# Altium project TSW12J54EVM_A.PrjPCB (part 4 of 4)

## Sheet TSW12J54EVM_A_8_Hardware.SchDoc
size 431 x 279 mm; Date: Not shown in title block; ApprovedBy: Not shown in title block; CheckedBy: Not shown in title block; Author: Not shown in title block; CompanyName: Not shown in title block; Engineer: Not shown in title block; Organization: Not shown in title block; Address1: Not shown in title block; Address2: Not shown in title block; Address3: Not shown in title block; Address4: Not shown in title block; DocumentNumber: 8; Revision: Use project parameter SCH_Rev; SheetNumber: 8; SheetTotal: 8; PageSetup: Record=PageOptions¦CenterHorizontal=True¦CenterVertical=True¦PrintScale=1.00¦XCorrection=1.00¦YCorrection=1.00¦PrintKind=0¦BorderSize=5000000¦LeftOffset=0¦BottomOffset=0¦Orientation=2¦PaperLength=1000¦PaperWidth=1000¦Scale=100¦PaperSource=15¦PrintQuality=600¦MediaType=1¦DitherType=10¦PaperKind=Letter¦PrintScaleMode=1
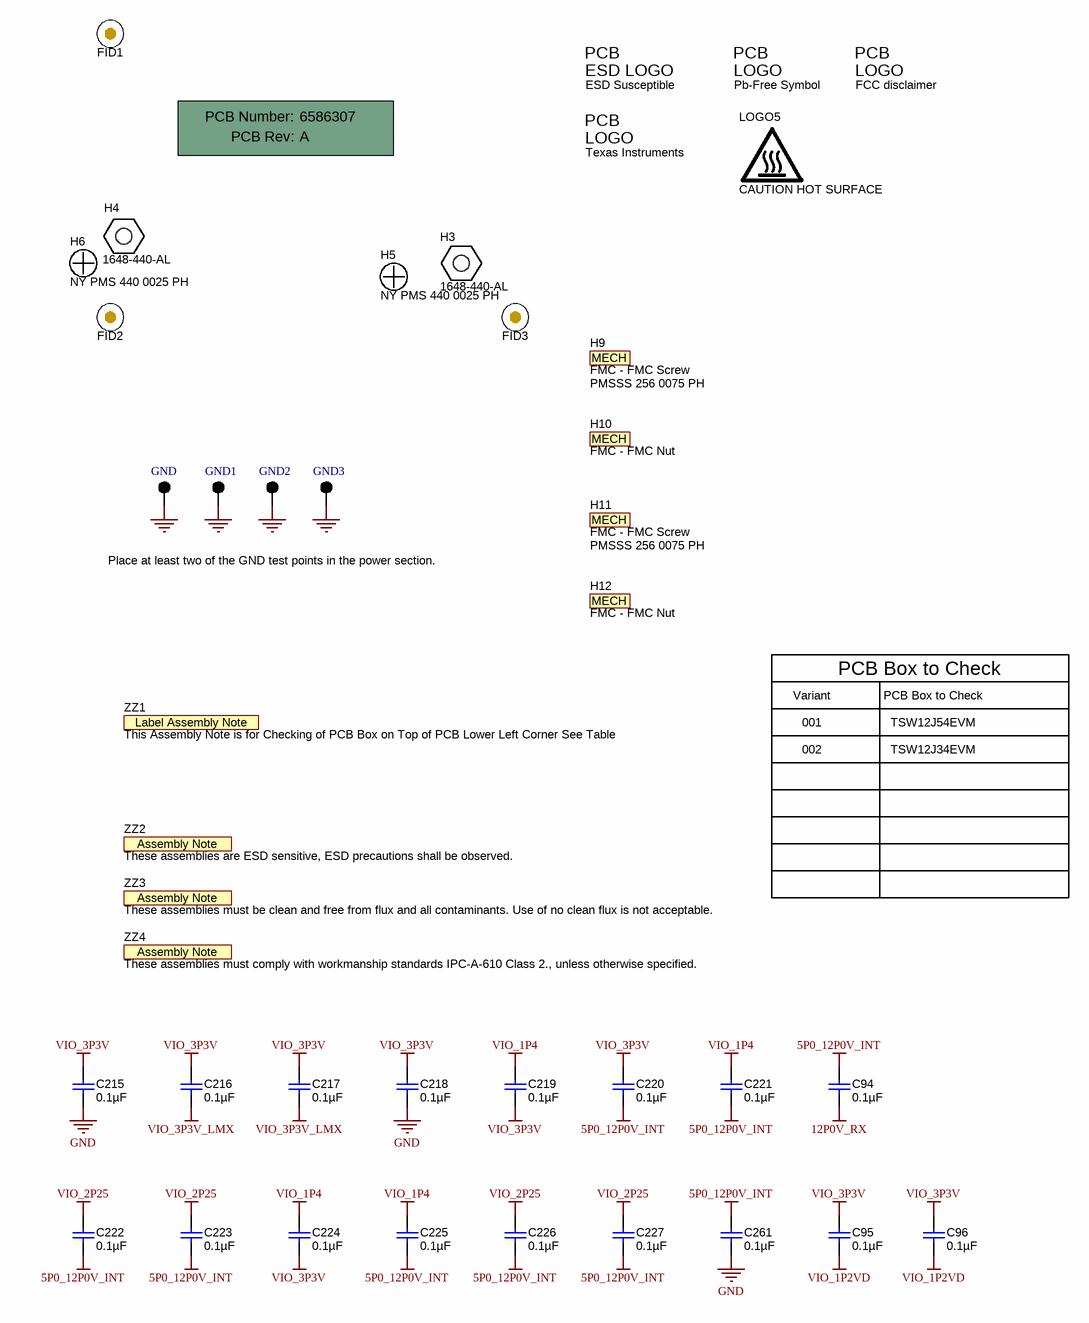
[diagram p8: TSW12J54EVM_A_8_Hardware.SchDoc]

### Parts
!PCB  Printed Circuit Board  (value not drawn)  (mechanical)
C94  ValueDisplayed: 0.1µF  [0402L]  (hidden comment: GRM155R71A104KA01D)
C95  ValueDisplayed: 0.1µF  [0402L]  (hidden comment: GRM155R71A104KA01D)
C96  ValueDisplayed: 0.1µF  [0402L]  (hidden comment: GRM155R71A104KA01D)
C215  ValueDisplayed: 0.1µF  [0402L]  (hidden comment: GRM155R71A104KA01D)
C216  ValueDisplayed: 0.1µF  [0402L]  (hidden comment: GRM155R71A104KA01D)
C217  ValueDisplayed: 0.1µF  [0402L]  (hidden comment: GRM155R71A104KA01D)
C218  ValueDisplayed: 0.1µF  [0402L]  (hidden comment: GRM155R71A104KA01D)
C219  ValueDisplayed: 0.1µF  [0402L]  (hidden comment: GRM155R71A104KA01D)
C220  ValueDisplayed: 0.1µF  [0402L]  (hidden comment: GRM155R71A104KA01D)
C221  ValueDisplayed: 0.1µF  [0402L]  (hidden comment: GRM155R71A104KA01D)
C222  ValueDisplayed: 0.1µF  [0402L]  (hidden comment: GRM155R71A104KA01D)
C223  ValueDisplayed: 0.1µF  [0402L]  (hidden comment: GRM155R71A104KA01D)
C224  ValueDisplayed: 0.1µF  [0402L]  (hidden comment: GRM155R71A104KA01D)
C225  ValueDisplayed: 0.1µF  [0402L]  (hidden comment: GRM155R71A104KA01D)
C226  ValueDisplayed: 0.1µF  [0402L]  (hidden comment: GRM155R71A104KA01D)
C227  ValueDisplayed: 0.1µF  [0402L]  (hidden comment: GRM155R71A104KA01D)
C261  ValueDisplayed: 0.1µF  [0402L]  (hidden comment: GRM155R71A104KA01D)
FID1  Fiducial  [Fiducial10-30]  (value not drawn)
FID2  Fiducial  [Fiducial10-30]  (value not drawn)
FID3  Fiducial  [Fiducial10-30]  (value not drawn)
GND  5011  [Keystone5011]  (value not drawn)
GND1  5011  [Keystone5011]  (value not drawn)
GND2  5011  [Keystone5011]  (value not drawn)
GND3  5011  [Keystone5011]  (value not drawn)
H3  1648-440-AL  [Keystone_1902C]
H4  1648-440-AL  [Keystone_1902C]
H5  NY PMS 440 0025 PH  [NY PMS 440 0025 PH]
H6  NY PMS 440 0025 PH  [NY PMS 440 0025 PH]
H9  FMC - FMC Screw  PartNumber: PMSSS 256 0075 PH  (mechanical)
H10  FMC - FMC Nut  (mechanical)
H11  FMC - FMC Screw  PartNumber: PMSSS 256 0075 PH  (mechanical)
H12  FMC - FMC Nut  (mechanical)
Logo1  ESD Susceptible  [ESD_Overlay_Small]  (no BOM)
Logo2  Texas Instruments  [TI_Symbol_Overlay_Small]  (no BOM)
Logo3  Pb-Free Symbol  [Pb-Free_Overlay_Small]  (no BOM)
Logo4  FCC disclaimer  [FCC_disclaimer]  (no BOM)
LOGO5  CAUTION HOT SURFACE  [IEC_HotSurface_Small]  (no BOM)
ZZ1  This Assembly Note is for Checking of PCB Box on Top of PCB Lower Left Corner See Table  [AssemblyNoteLabel]  (no BOM)
ZZ2  These assemblies are ESD sensitive, ESD precautions shall be observed.  [AssemblyNote]  (no BOM)
ZZ3  These assemblies must be clean and free from flux and all contaminants. Use of no clean flux is not acceptable.  [AssemblyNote]  (no BOM)
ZZ4  These assemblies must comply with workmanship standards IPC-A-610 Class 2., unless otherwise specified.  [AssemblyNote]  (no BOM)

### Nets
5P0_12P0V_INT: C94.1 C220.2 C221.2 C222.2 C223.2 C225.2 C226.2 C227.2 C261.1
12P0V_RX: C94.2
GND: C215.2 C218.2 C261.2 GND.1 GND1.1 GND2.1 GND3.1
VIO_1P2VD: C95.2 C96.2
VIO_1P4: C219.1 C221.1 C224.1 C225.1
VIO_2P25: C222.1 C223.1 C226.1 C227.1
VIO_3P3V: C95.1 C96.1 C215.1 C216.1 C217.1 C218.1 C219.2 C220.1 C224.2
VIO_3P3V_LMX: C216.2 C217.2

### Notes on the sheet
- Place at least two of the GND test points in the power section.
- Variant
- PCB Box to Check
- 001
- 002
- TSW12J54EVM
- TSW12J34EVM

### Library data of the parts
!PCB = PCB: Manufacturer: Any; PartNumber: 6586307; SymbolCreator: a0412235
C94-C96 C215-C227 C261 = GRM155R71A104KA01D: CAP, CERM, 0.1uF, 10V, +/-10%, X7R, 0402; Manufacturer: MuRata; Polarized: N; CompType: Capacitor; U/M: EA; Cap_F: 0.0000001; Tolerance_%: 10; TaMin_C: -55; TaMax_C: 125; Cap_Case: 0402
FID1-FID3 = Fiducial: Fiducial mark.  There is nothing to buy or mount.; SymbolCreator: codlsc
GND GND1-GND3 = 5011: Test Point, TH, Multipurpose, Black; Manufacturer: Keystone Electronics; CompType: Test Point Loop
H3 H4 = 1902C: Standoff, Round, 3/16"  x 1-3/16"L #4-40 Aluminum; Manufacturer: RAF; CompType: Hardware; U/M: EA
H5 H6 = NY PMS 440 0025 PH: Machine Screw, Round, #4-40 x 1/4, Nylon, Philips panhead; Manufacturer: B&F Fastener Supply; CompType: Hardware; SymbolCreator: codlsc; U/M: EA
H9 H11 = MechPart: MACHINE SCREW PAN PHILLIPS 2-56; Manufacturer: B&F Fastner Supply; SymbolCreator: codlsc; CompType: Mechanical; U/M: EA
H10 H12 = MechPart: HEX NUT 3/16" STN STEEL 2-56; Manufacturer: B & F Fastener Supply; PartNumber: HNSS256; SymbolCreator: codlsc; CompType: Mechanical; U/M: EA
Logo1 = ESD_Susceptible: ESD Susceptible Symbol; SymbolCreator: codlsc
Logo2 = TI_Logo: Texas Instrument Corporate Signature; SymbolCreator: codlsc
Logo3 = Pb-Free: SymbolCreator: a0412235
Logo4 = FCC_disclaimer: SymbolCreator: codlsc
LOGO5 = IEC_HotSurface: IEC 61010-1 Hot Surface Warning; SymbolCreator: a0412235
ZZ1 = AssemblyNoteLabel: SymbolCreator: a0412235
ZZ2-ZZ4 = AssemblyNote: SymbolCreator: codlsc

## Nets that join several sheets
5P0_12P0V_INT: TSW12J54EVM_A_5_Power (16 pins), TSW12J54EVM_A_8_Hardware (9 pins)
12P0V_RX: TSW12J54EVM_A_2_FMC (FMC_RX1.C35 FMC_RX1.C37), TSW12J54EVM_A_5_Power (EXT5V_FMC12V.3), TSW12J54EVM_A_8_Hardware (C94.2)
GND: TSW12J54EVM_A_1_ADC_IO (110 pins), TSW12J54EVM_A_2_FMC (164 pins), TSW12J54EVM_A_3_TRF3765 (64 pins), TSW12J54EVM_A_4_LMK04828 (33 pins), TSW12J54EVM_A_5_Power (80 pins), TSW12J54EVM_A_6_Power (20 pins), TSW12J54EVM_A_7_InterfaceControl (20 pins), TSW12J54EVM_A_8_Hardware (7 pins)
VIO_1P2VA: TSW12J54EVM_A_1_ADC_IO (18 pins), TSW12J54EVM_A_5_Power (C177.1 C188.1 L15.2)
VIO_1P2VD: TSW12J54EVM_A_1_ADC_IO (28 pins), TSW12J54EVM_A_5_Power (C189.1 C197.1 L16.2), TSW12J54EVM_A_8_Hardware (C95.2 C96.2)
VIO_1P4: TSW12J54EVM_A_5_Power (5 pins), TSW12J54EVM_A_8_Hardware (C219.1 C221.1 C224.1 C225.1)
VIO_1P9V: TSW12J54EVM_A_1_ADC_IO (20 pins), TSW12J54EVM_A_5_Power (6 pins), TSW12J54EVM_A_6_Power (R170.1 R173.1), TSW12J54EVM_A_7_InterfaceControl (C130.1 R123.2 U12.15)
VIO_2P25: TSW12J54EVM_A_5_Power (5 pins), TSW12J54EVM_A_8_Hardware (C222.1 C223.1 C226.1 C227.1)
VIO_3P3V: TSW12J54EVM_A_1_ADC_IO (15 pins), TSW12J54EVM_A_5_Power (C153.1 C163.1 L9.2), TSW12J54EVM_A_7_InterfaceControl (FTDI_3P3V.1 J3.2), TSW12J54EVM_A_8_Hardware (9 pins)
VIO_3P3V_LMK_CLK: TSW12J54EVM_A_4_LMK04828 (6 pins), TSW12J54EVM_A_5_Power (C116.1 C171.1 L13.2), TSW12J54EVM_A_7_InterfaceControl (R131.1)
VIO_3P3V_LMK_PLL: TSW12J54EVM_A_4_LMK04828 (16 pins), TSW12J54EVM_A_5_Power (C164.1 C165.1 L10.2)
VIO_3P3V_LMX: TSW12J54EVM_A_3_TRF3765 (19 pins), TSW12J54EVM_A_5_Power (C144.1 C152.1 L6.2), TSW12J54EVM_A_7_InterfaceControl (R130.1), TSW12J54EVM_A_8_Hardware (C216.2 C217.2)
VIO_3P75: TSW12J54EVM_A_1_ADC_IO (11 pins), TSW12J54EVM_A_6_Power (C280.1 C281.1 L43.2)
VIO_4P05V: TSW12J54EVM_A_5_Power (6 pins), TSW12J54EVM_A_6_Power (L35.1 L36.1)
VIO_-1P25: TSW12J54EVM_A_1_ADC_IO (10 pins), TSW12J54EVM_A_6_Power (C289.1 C290.1 L44.2)
ADC_OR_T0: TSW12J54EVM_A_1_ADC_IO (D2.2 OR.3 U2.25), TSW12J54EVM_A_2_FMC (FMC_RX1.G27)
ADC_OR_T1: TSW12J54EVM_A_1_ADC_IO (D4.2 OR.1 U2.26), TSW12J54EVM_A_2_FMC (FMC_RX1.D26)
D0_N: TSW12J54EVM_A_1_ADC_IO (C9.1), TSW12J54EVM_A_2_FMC (FMC_RX1.C6)
D0_P: TSW12J54EVM_A_1_ADC_IO (C7.1), TSW12J54EVM_A_2_FMC (FMC_RX1.C7)
D1_N: TSW12J54EVM_A_1_ADC_IO (C12.1), TSW12J54EVM_A_2_FMC (FMC_RX1.A2)
D1_P: TSW12J54EVM_A_1_ADC_IO (C10.1), TSW12J54EVM_A_2_FMC (FMC_RX1.A3)
D2_N: TSW12J54EVM_A_1_ADC_IO (C14.1), TSW12J54EVM_A_2_FMC (FMC_RX1.A6)
D2_P: TSW12J54EVM_A_1_ADC_IO (C13.1), TSW12J54EVM_A_2_FMC (FMC_RX1.A7)
D3_N: TSW12J54EVM_A_1_ADC_IO (C17.1), TSW12J54EVM_A_2_FMC (FMC_RX1.A10)
D3_P: TSW12J54EVM_A_1_ADC_IO (C15.1), TSW12J54EVM_A_2_FMC (FMC_RX1.A11)
D4_N: TSW12J54EVM_A_1_ADC_IO (C21.1), TSW12J54EVM_A_2_FMC (FMC_RX1.A14)
D4_P: TSW12J54EVM_A_1_ADC_IO (C20.1), TSW12J54EVM_A_2_FMC (FMC_RX1.A15)
D5_N: TSW12J54EVM_A_1_ADC_IO (C23.1), TSW12J54EVM_A_2_FMC (FMC_RX1.A18)
D5_P: TSW12J54EVM_A_1_ADC_IO (C22.1), TSW12J54EVM_A_2_FMC (FMC_RX1.A19)
D6_N: TSW12J54EVM_A_1_ADC_IO (C28.1), TSW12J54EVM_A_2_FMC (FMC_RX1.B16)
D6_P: TSW12J54EVM_A_1_ADC_IO (C26.1), TSW12J54EVM_A_2_FMC (FMC_RX1.B17)
D7_N: TSW12J54EVM_A_1_ADC_IO (C31.1), TSW12J54EVM_A_2_FMC (FMC_RX1.B12)
D7_P: TSW12J54EVM_A_1_ADC_IO (C29.1), TSW12J54EVM_A_2_FMC (FMC_RX1.B13)
DEV_CLK_N: TSW12J54EVM_A_1_ADC_IO (C263.2), TSW12J54EVM_A_4_LMK04828 (R160.2)
DEV_CLK_P: TSW12J54EVM_A_1_ADC_IO (C262.2), TSW12J54EVM_A_4_LMK04828 (R161.2)
DEVCLKARX_N: TSW12J54EVM_A_2_FMC (FMC_RX1.D5), TSW12J54EVM_A_4_LMK04828 (R60.2)
DEVCLKARX_P: TSW12J54EVM_A_2_FMC (FMC_RX1.D4), TSW12J54EVM_A_4_LMK04828 (R59.2)
DEVCLKBRX_N: TSW12J54EVM_A_2_FMC (FMC_RX1.G7), TSW12J54EVM_A_4_LMK04828 (R63.2)
DEVCLKBRX_P: TSW12J54EVM_A_2_FMC (FMC_RX1.G6), TSW12J54EVM_A_4_LMK04828 (R64.2)
FMC_DEVCLK_N: TSW12J54EVM_A_1_ADC_IO (C93.2), TSW12J54EVM_A_2_FMC (FMC_RX1.K29)
FMC_DEVCLK_P: TSW12J54EVM_A_1_ADC_IO (C92.2), TSW12J54EVM_A_2_FMC (FMC_RX1.K28)
FMC_SYSREF_N: TSW12J54EVM_A_1_ADC_IO (C91.2), TSW12J54EVM_A_2_FMC (FMC_RX1.K38)
FMC_SYSREF_P: TSW12J54EVM_A_1_ADC_IO (C90.2), TSW12J54EVM_A_2_FMC (FMC_RX1.K37)
FTDI_TRF_R1: TSW12J54EVM_A_3_TRF3765 (U4.6), TSW12J54EVM_A_7_InterfaceControl (U13.43)
LMK04828_CSb: TSW12J54EVM_A_4_LMK04828 (U6.18), TSW12J54EVM_A_7_InterfaceControl (R68.1 R69.1 R98.1 R104.2)
LMK04828_RESET: TSW12J54EVM_A_2_FMC (FMC_RX1.J16), TSW12J54EVM_A_4_LMK04828 (R122.2 U6.5)
LMK04828_SYNC: TSW12J54EVM_A_2_FMC (FMC_RX1.J15), TSW12J54EVM_A_4_LMK04828 (R142.1)
LMK_TRF_CLK: TSW12J54EVM_A_3_TRF3765 (U4.4), TSW12J54EVM_A_4_LMK04828 (U6.19), TSW12J54EVM_A_7_InterfaceControl (R102.1 R115.1 R121.1 R129.2)
LMK_TRF_DATA: TSW12J54EVM_A_3_TRF3765 (U4.3), TSW12J54EVM_A_4_LMK04828 (U6.20), TSW12J54EVM_A_7_InterfaceControl (R101.1 R114.1 R120.1 R128.2)
NetC87_2: TSW12J54EVM_A_1_ADC_IO (C89.1 DEVCLK.1 R165.2), TSW12J54EVM_A_4_LMK04828 (C87.2)
NetFMC_RX1_C30: TSW12J54EVM_A_2_FMC (FMC_RX1.C30 J1.2 U16.6), TSW12J54EVM_A_7_InterfaceControl (R127.2)
NetFMC_RX1_C31: TSW12J54EVM_A_2_FMC (FMC_RX1.C31 J1.1 U16.5), TSW12J54EVM_A_7_InterfaceControl (R126.2)
NetFMC_RX1_E12: TSW12J54EVM_A_1_ADC_IO (R136.2), TSW12J54EVM_A_2_FMC (FMC_RX1.E12)
NetFMC_RX1_E13: TSW12J54EVM_A_1_ADC_IO (R137.2), TSW12J54EVM_A_2_FMC (FMC_RX1.E13)
NetFMC_RX1_E36: TSW12J54EVM_A_1_ADC_IO (R138.2), TSW12J54EVM_A_2_FMC (FMC_RX1.E36)
NetFMC_RX1_G30: TSW12J54EVM_A_2_FMC (FMC_RX1.G30), TSW12J54EVM_A_7_InterfaceControl (R121.2)
NetFMC_RX1_G33: TSW12J54EVM_A_2_FMC (FMC_RX1.G33), TSW12J54EVM_A_7_InterfaceControl (R69.2)
NetFMC_RX1_G34: TSW12J54EVM_A_2_FMC (FMC_RX1.G34), TSW12J54EVM_A_7_InterfaceControl (R119.2)
NetFMC_RX1_G36: TSW12J54EVM_A_2_FMC (FMC_RX1.G36), TSW12J54EVM_A_7_InterfaceControl (R57.2)
NetFMC_RX1_G37: TSW12J54EVM_A_2_FMC (FMC_RX1.G37), TSW12J54EVM_A_7_InterfaceControl (R55.2)
NetFMC_RX1_H34: TSW12J54EVM_A_2_FMC (FMC_RX1.H34), TSW12J54EVM_A_7_InterfaceControl (R120.2)
NetFMC_RX1_H37: TSW12J54EVM_A_2_FMC (FMC_RX1.H37), TSW12J54EVM_A_7_InterfaceControl (R58.2)
NetFMC_RX1_H38: TSW12J54EVM_A_2_FMC (FMC_RX1.H38), TSW12J54EVM_A_7_InterfaceControl (R54.2)
NetR31_1: TSW12J54EVM_A_1_ADC_IO (R31.1 U3.12), TSW12J54EVM_A_7_InterfaceControl (R117.1 R124.1 R126.1)
NetR32_1: TSW12J54EVM_A_1_ADC_IO (R32.1 U3.13), TSW12J54EVM_A_7_InterfaceControl (R125.1 R127.1)
NetR54_1: TSW12J54EVM_A_1_ADC_IO (U2.59), TSW12J54EVM_A_7_InterfaceControl (R54.1 R118.1 R139.2 SPI.2)
NetR55_1: TSW12J54EVM_A_1_ADC_IO (U2.56), TSW12J54EVM_A_7_InterfaceControl (R55.1 R110.1 SPI.4)
NetR57_1: TSW12J54EVM_A_1_ADC_IO (U2.57), TSW12J54EVM_A_7_InterfaceControl (R57.1 R111.1 R140.2 SPI.6)
NetR58_1: TSW12J54EVM_A_1_ADC_IO (U2.58), TSW12J54EVM_A_7_InterfaceControl (R58.1 R109.1 R141.2 SPI.8)
SYNC_N: TSW12J54EVM_A_1_ADC_IO (R20.2), TSW12J54EVM_A_2_FMC (FMC_RX1.G13)
SYNC_P: TSW12J54EVM_A_1_ADC_IO (R19.2), TSW12J54EVM_A_2_FMC (FMC_RX1.G12)
SYNC_SE: TSW12J54EVM_A_1_ADC_IO (R134.1), TSW12J54EVM_A_2_FMC (FMC_RX1.H31), TSW12J54EVM_A_4_LMK04828 (R143.1)
SYSREFRX_N: TSW12J54EVM_A_2_FMC (FMC_RX1.G10), TSW12J54EVM_A_4_LMK04828 (R61.2)
SYSREFRX_P: TSW12J54EVM_A_2_FMC (FMC_RX1.G9), TSW12J54EVM_A_4_LMK04828 (R62.2)
SYSREFTX_N: TSW12J54EVM_A_1_ADC_IO (C37.2), TSW12J54EVM_A_4_LMK04828 (R43.2)
SYSREFTX_P: TSW12J54EVM_A_1_ADC_IO (C35.2), TSW12J54EVM_A_4_LMK04828 (R44.2)
TRF3765_STROBE: TSW12J54EVM_A_3_TRF3765 (U4.5), TSW12J54EVM_A_7_InterfaceControl (R97.1 R113.1 R116.2 R119.1)
TRF_OutA_N: TSW12J54EVM_A_3_TRF3765 (R157.1 R159.2 U17.6), TSW12J54EVM_A_4_LMK04828 (C112.2)
TRF_OutA_P: TSW12J54EVM_A_3_TRF3765 (R156.1 R158.2 U17.7), TSW12J54EVM_A_4_LMK04828 (C113.2)
TRF_OutB_N: TSW12J54EVM_A_1_ADC_IO (C33.2), TSW12J54EVM_A_3_TRF3765 (C83.2 R36.2)
TRF_OutB_P: TSW12J54EVM_A_1_ADC_IO (C32.2), TSW12J54EVM_A_3_TRF3765 (C75.2 R29.2)

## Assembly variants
001_TSW12J54EVM: not fitted C30 C36 C85 C86 C87 C90 C91 C92 C93 C114 C123 C230 C231 C234 C235 C247 C250 C251 C262 C263 FID1 FID2 FID3 R7 R8 R9 R18 R21 R22 R23 R24 R26 R29 R30 R36 R40 R42 R50 R54 R55 R57 R58 R69 R73 R75 R83 R84 R90 R92 R95 R104 R116 R119 R120 R121 R126 R127 R128 R129 R139 R140 R141 R142 R146 R151 R153 R165 R181 U16
002_TSW12J34EVM: not fitted C30 C36 C85 C86 C87 C90 C91 C92 C93 C114 C123 C230 C231 C234 C235 C247 C250 C251 C262 C263 FID1 FID2 FID3 R6 R7 R8 R18 R21 R22 R23 R24 R26 R29 R30 R36 R40 R42 R50 R54 R55 R57 R58 R69 R73 R75 R83 R84 R90 R92 R95 R104 R116 R119 R120 R121 R126 R127 R128 R129 R139 R140 R141 R142 R146 R151 R153 R165 R181 Rf+ Rf- U16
